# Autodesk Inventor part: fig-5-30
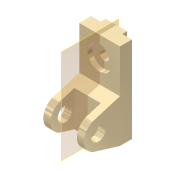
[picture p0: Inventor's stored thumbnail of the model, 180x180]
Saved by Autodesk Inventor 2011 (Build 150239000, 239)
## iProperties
Shininess: 65.0
Angle Display Precision: 2
Document Length Units: 11269
Document Angle Units: 11279
Document Time Units: 11290
Document Mass Units: 11283
Document Length Units Precision: 3
Document Angle Units Precision: 2
Created: 2001-11
Part Number: fig-5-30
Document SubType Name: Modeling
Designer: Renu Muthoo
Density: 1 g/cm^3
Density: 0.0
Volumn: 0.0
Area: 0.0
PropertySet Name: Model Information
Control State: 0
Master: False
Checked Out: False
Author: Renu Muthoo
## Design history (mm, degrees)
node "Sketch1"
sketch "Sketch2"
  geometry: L1 (33.257, 104.664)-(33.257, -75.336); L2 (33.257, -75.336)-(8.257, -75.336); L3 (8.257, -75.336)-(-45.451, -59.045); L4 (-45.451, -1.628)-(8.257, 14.664); L5 (8.257, 14.664)-(8.257, 104.664); L6 (8.257, 104.664)-(33.257, 104.664); C1 r 15 at (-36.743, -30.336); A1 r 30 centre (-36.743, -30.336) between (-45.451, -1.628) and (-45.451, -59.045)
  constraints: 12 end point, 2 centre point, 2 equal length, 2 parallel, 2 point on circle, 2 tangent, 1 coincident, 1 perpendicular, 1 vertical
  dimensions: "d0" = 180 distance of L1.start L1.end; "d1" = 30 radius of A1; "d2" = 25 distance of L5.end L1.start; "d3" = 45 distance from line of L2 A1.centre; "d4" = 70 distance from line of L1 A1.centre; "d5" = 30 diameter of C1
extrude "Extrusion1" new body sketch "Sketch2" distance "d6" = 85; taper "d7" = 0 deg
workplane "Work Plane1"
sketch "Sketch3"
  geometry: L1 (15, 62.364)-(70, 62.364); L2 (70, 62.364)-(70, -52.386); L3 (70, -52.386)-(15, -52.386); L4 (15, -52.386)-(15, 62.364); L5 (0, -45)-(0, -28.708) reference
  constraints: 8 end point, 2 parallel, 1 horizontal, 1 perpendicular
  dimensions: "d8" = 55 distance of L1.start L1.end; "d9" = 15 distance between parallel lines of L5 L4
extrude "Extrusion2" cut sketch "Sketch3" distance "d10" = 50; taper "d11" = 0 deg
sketch "Sketch4"
  geometry: L1 (0, 25)-(85, 25) reference; L2 (0, 0)-(0, 25) reference; L3 (20, 25)-(65, 25); L4 (65, 25)-(65, 35); L5 (65, 35)-(20, 35); L6 (20, 35)-(20, 25)
  constraints: 8 end point, 2 parallel, 1 horizontal, 1 perpendicular, 1 point on line
  dimensions: "d12" = 45 distance of L4.end L5.end; "d13" = 10 distance of L3.end L4.end; "d14" = 20 distance between parallel lines of L2 L6
extrude "Extrusion3" join sketch "Sketch4" stored distance "d15" = 50; taper "d16" = 0 deg
sketch "Sketch5"
  geometry: L1 (85, 0)-(85, 90) reference; L2 (0, 90)-(85, 90) reference; 1 further point
  dimensions: "d17" = 42 distance from line of L2 point (42.5, 48); "d18" = 42.5 distance from line of L1 point (42.5, 48)
hole "Hole1" sketch "Sketch5" at (42.5, 48) diameter "d19" = 20; stored, may be unused: countersink angle "d23" = 82 deg, drill point angle "d25" = 118 deg; dims "d20" = 6, "d21" = 50, "d22" = 10, "d24" = 8
workplane "Work Plane5"
body "Solid1"
